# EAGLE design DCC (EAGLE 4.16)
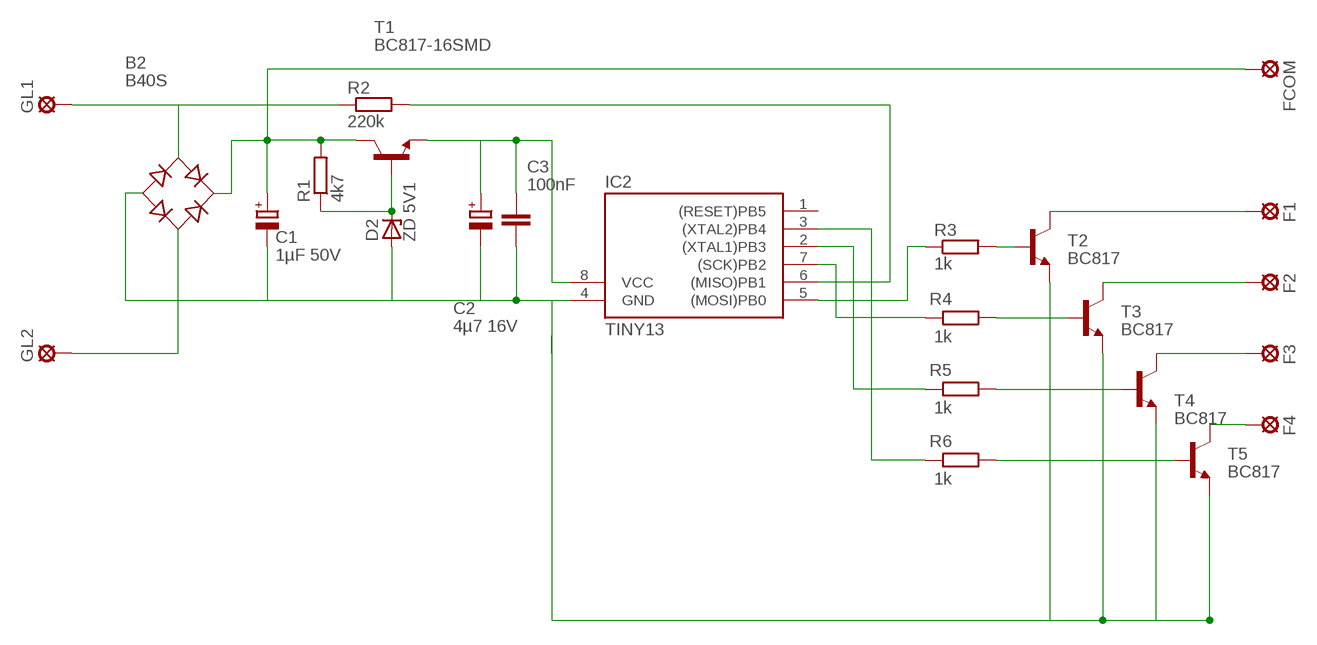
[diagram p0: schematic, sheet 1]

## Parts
B2  B40S  RECTIFIER-B40S  [B40S]
C1  1µF 50V  CPOL-EUCT3528  [CT3528]
C2  4µ7 16V  CPOL-EUCT3528  [CT3528]
C3  100nF  C-EUC0603K  [C0603K]
D2  ZD 5V1  ZENER-DIODESOD80C  [SOD80C]
F1  LSP10  [LSP10]
F2  LSP10  [LSP10]
F3  LSP10  [LSP10]
F4  LSP10  [LSP10]
FCOM  LSP10  [LSP10]
GL1  GL1  LSP10  [LSP10]
GL2  LSP10  [LSP10]
IC2  TINY13  TINY12S  [SOIC8]
R1  4k7  R-EU_R0805  [R0805]
R2  220k  R-EU_R0805  [R0805]
R3  1k  R-EU_R0805  [R0805]
R4  1k  R-EU_R0805  [R0805]
R5  1k  R-EU_R0805  [R0805]
R6  1k  R-EU_R0805  [R0805]
T1  BC817-16SMD  [SOT23-BEC]
T2  BC817  BC847  [SOT23]
T3  BC817  BC847  [SOT23]
T4  BC817  BC847  [SOT23]
T5  BC817  BC847  [SOT23]

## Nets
GND: B2.- C1.- C2.- C3.2 D2.A IC2.4(GND) T2.2(E) T3.2(E) T4.2(E) T5.2(E)
N$1: B2.AC1 GL1.MP R2.1
N$2: B2.AC2 GL2.MP
N$3: R3.2 T2.1(B)
N$4: R4.1 T3.1(B)
N$5: IC2.5((MOSI)PB0) R3.1
N$6: IC2.6((MISO)PB1) R2.2
N$7: D2.C R1.1 T1.B
N$8: B2.+ C1.+ FCOM.MP R1.2 T1.C
N$9: IC2.7((SCK)PB2) R4.2
N$10: F1.MP T2.3(C)
N$11: F2.MP T3.3(C)
N$12: IC2.3((XTAL2)PB4) R6.2
N$13: IC2.2((XTAL1)PB3) R5.2
N$14: R6.1 T5.1(B)
N$15: F4.MP T5.3(C)
N$16: F3.MP T4.3(C)
N$17: R5.1 T4.1(B)
VCC: C2.+ C3.1 IC2.8(VCC) T1.E
Unconnected: IC2.1((RESET)PB5)

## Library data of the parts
B2 = rectifier:RECTIFIER-: Rectifier
C1 C2 = rcl:CPOL-EU: POLARIZED CAPACITOR, European symbol
C3 = rcl:C-EU: CAPACITOR, European symbol
D2 = diode:ZENER-DIODE: Z-Diode
F1-F4 FCOM GL1 GL2 = solpad:LSP10: SOLDER PAD
IC2 = atmel:TINY12*: MICROCONTROLLER 1 Kbytes FLASH 64 bytes EEPROM
R1-R6 = rcl:R-EU_: RESISTOR, European symbol
T1 = transistor-npn:BC817*: NPN Transistor
T2-T5 = transistor:BC847: NPN TRANSISTOR

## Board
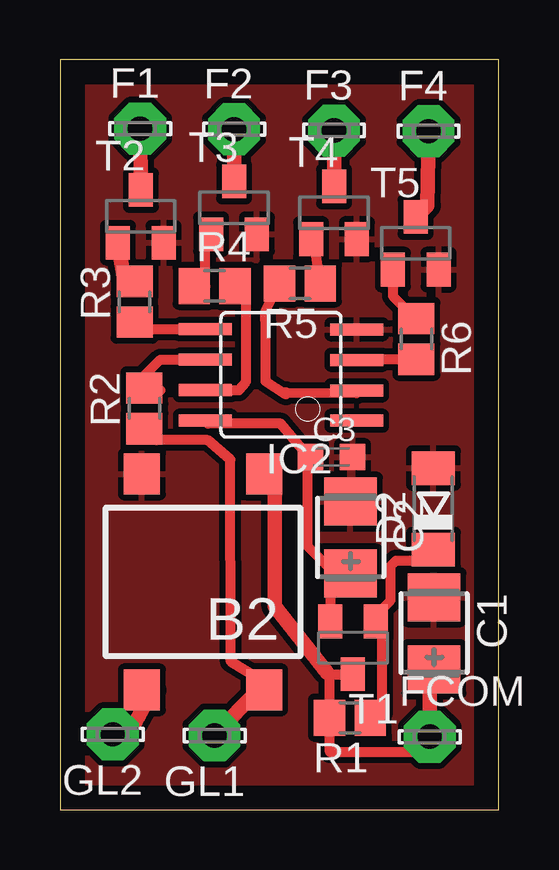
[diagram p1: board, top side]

Size 18.29 x 31.26 mm. Coordinates in mm from the lower left corner, seen from the top.
Outline: 0,0 18.29,0 18.29,31.26 0,31.26 0,0
Copper layers (1*16): Top 0.035mm / dielectric 1.5mm / Bottom 0.035mm
Design rules "Bilex DRU": minimum track width 10mil, minimum drill 24mil, track to track 10mil, track to pad 10mil, pad to pad 10mil, via to via 10mil, smd to smd 10mil, copper to edge 40mil, drill to drill 8mil, minimum pad ring 10mil, minimum via ring 8mil, stop-mask expansion 4mil, vias tented up to drill 0mil, thermal gap 10mil

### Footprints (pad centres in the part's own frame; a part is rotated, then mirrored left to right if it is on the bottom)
B40S = smd 1.5 x 1.7: + -2.55,-4.5; - 2.55,-4.5; AC1 -2.55,4.5; AC2 2.55,4.5
CT3528 = smd 2 x 2.2: + 1.5,0; - -1.5,0
C0603K = smd 1.05 x 1.08: 1 -0.875,0; 2 0.875,0
SOD80C = smd 1.4 x 1.8: A 1.7,0; C -1.7,0
LSP10 = drill 1.016 pad 2.159 octagon: MP 0,0
SOIC8 = smd 0.5 x 2.2: 1 -1.905,-3.154; 2 -0.645,-3.154; 3 0.625,-3.154; 4 1.895,-3.154; 5 1.905,3.154; 6 0.635,3.154; 7 -0.635,3.154; 8 -1.905,3.154
R0805 = smd 1.3 x 1.5: 1 -0.85,0; 2 0.85,0
SOT23-BEC = smd 1 x 1.4: B -0.95,-1.1; C 0,1.1; E 0.95,-1.1
SOT23 = smd 1 x 1.4: 1 -0.95,-1.1; 2 0.95,-1.1; 3 0,1.1

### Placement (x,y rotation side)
B2  5.96,9.49 180 top
C1  15.58,7.36 270 top
C2  12.1,11.35 270 top
C3  11.32,14.7 0 top
D2  15.56,12.54 90 top
F1  3.34,28.39 0 top
F2  7.25,28.37 0 top
F3  11.42,28.32 0 top
F4  15.35,28.29 0 top
FCOM  15.41,3.04 0 top
GL1  6.44,3.09 180 top
GL2  2.2,3.14 180 top
IC2  9.21,18.13 90 top
R1  12.08,3.83 180 top
R2  3.52,16.73 90 top
R3  3.11,21.18 90 top
R4  6.44,21.84 0 top
R5  9.99,21.94 180 top
R6  14.85,19.63 270 top
T1  12.2,6.75 180 top
T2  3.37,24.73 0 top
T3  7.25,25.09 0 top
T4  11.42,24.89 0 top
T5  14.82,23.62 0 top

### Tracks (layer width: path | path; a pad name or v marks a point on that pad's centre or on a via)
GND
  pour Top: 0.44,30.2 18.07,30.2 18.12,0.76 0.5,0.76
N$1
  Top 0.406: B2.AC1 8.96,5.04 7.12,6.17 7.1,14.6 6.16,15.41 4.03,15.41 3.56,15.88 R2.1
  Top 0.61: GL1.MP 6.46,3.12 6.44,3.14 8.29,4.99 B2.AC1
N$2
  Top 0.61: B2.AC2 3.87,4.98 2.86,3.14 GL2.MP
N$3
  Top 0.61: R3.2 3.11,21.94 2.67,22.13 T2.1
N$4
  Top 0.406: T3.1 6.48,23.96 6.06,23.52 6.06,21.81 R4.1
N$5
  Top 0.406: R3.1 3.12,20.33 3.42,20.04 IC2.5
N$6
  Top 0.406: 4.18,17.5 4.15,17.47 R2.2 3.51,17.58 3.49,17.6 3.52,17.62 3.52,18.11 4.18,18.77 IC2.6
N$7
  Top 0.406: R1.1 12.89,4.03 12.89,4.06 13.42,4.06 13.42,8.21 T1.B 13.14,7.86 13.14,8.1 13.78,8.73 13.78,10.16 14.01,10.38 15.1,10.38 D2.C
N$8
  Top 0.406: 11.21,4.03 R1.2 11.24,3.83 11.24,2.41 | 11.19,5.66 11.21,5.66 11.21,5.65 | 11.19,5.66 11.14,5.71 | 11.21,5.65 T1.C | 11.21,5.65 11.19,5.66 | 11.21,5.65 11.24,5.63 11.24,2.41 | FCOM.MP 15.41,3.02 14.8,2.41 11.24,2.41
  Top 0.61: B2.+ 8.95,13.99 8.95,8.48 11.14,5.71 | C1.+ 15.05,5.61 15.41,5.25 FCOM.MP
N$9
  Top 0.406: R4.2 7.73,21.79 7.76,20.57 7.76,17.85 7.46,17.5 IC2.7
N$10
  Top 0.61: T2.3 F1.MP
N$11
  Top 0.61: T3.3 F2.MP
N$12
  Top 0.406: IC2.3 12.49,18.76 12.51,18.74 12.55,18.78 R6.2
N$13
  Top 0.406: IC2.2 12.36,17.37 9.41,17.39 | 9.41,17.39 9.35,17.39 | R5.2 8.56,20.76 8.57,19.96 8.57,17.85 9.41,17.32 9.41,17.39
N$14
  Top 0.406: R6.1 14.81,20.48 13.87,21.42 T5.1
N$15
  Top 0.61: T5.3 15.3,25.19 F4.MP
N$16
  Top 0.61: T4.3 F3.MP
N$17
  Top 0.406: R5.1 10.59,23.68 10.58,24.02 10.48,23.9 10.49,23.91 T4.1
VCC
  Top 0.406: 10.33,14.78 10.33,10.97 11.42,9.88 12.08,9.88 12.08,9.87 C2.+ 11.29,9.04 11.29,7.87 11.27,7.87 T1.E | 10.33,14.78 9.21,16.1 6.16,16.1 IC2.8 | 10.48,14.7 10.48,14.68 | 10.48,14.7 C3.1 | 10.33,14.78 10.48,14.78 10.48,14.7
